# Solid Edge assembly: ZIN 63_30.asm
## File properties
Title: Zylinder
Author: bmolnar
Template: iso metric assembly.asm
Last saved by: bmolnar
Revision: 12
Application: Solid Edge
Username: bmolnar
Dokumentum tartalom típus: 1
Document Number: ZIN 63/30
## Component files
Kit_1.par
Kit_2.par
Kolbenstange.par
Profilrohr.par
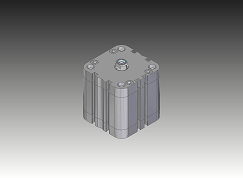
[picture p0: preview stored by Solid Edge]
